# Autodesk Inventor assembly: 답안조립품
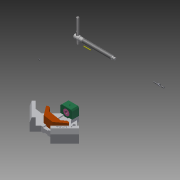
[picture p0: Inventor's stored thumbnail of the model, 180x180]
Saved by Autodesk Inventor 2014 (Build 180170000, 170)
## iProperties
Created: 2020-05
Part Number: 답안조립품
Document SubType Name: Assembly
Designer: kh
Author: kh
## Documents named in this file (11)
- C:\Users\kh\Desktop\700506V1026\답안조립품.iam
- C:\Users\kh\Desktop\700506V1026\본체.ipt
- C:\Users\kh\Desktop\700506V1026\리드스크류.ipt
- C:\Users\kh\Desktop\700506V1026\멈춤나사 M4x5.ipt
- C:\Users\kh\Desktop\700506V1026\멈춤나사 M4x10.ipt
- C:\Users\kh\Desktop\700506V1026\볼트 M4x16.ipt
- C:\Users\kh\Desktop\700506V1026\부시.ipt
- C:\Users\kh\Desktop\700506V1026\서포트.ipt
- C:\Users\kh\Desktop\700506V1026\조.ipt
- C:\Users\kh\Desktop\700506V1026\평행 핀 2.5x24.ipt
- C:\Users\kh\Desktop\700506V1026\핸들.ipt
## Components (1 placed, 1 different names)
1. 핸들:1 — Mate:3
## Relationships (1: Mate 1)
- Mate:3: 핸들:1
